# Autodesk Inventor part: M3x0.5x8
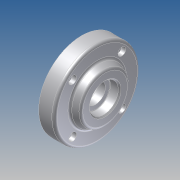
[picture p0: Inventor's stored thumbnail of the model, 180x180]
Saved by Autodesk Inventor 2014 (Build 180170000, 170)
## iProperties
Company: 한국ATC센터
Created: 2009-02
Part Number: M3x0.5x8
Document SubType Name: Modeling
Designer: KYOUNG IL JANG
Density: 2.71 g/cm^3
Mass: 114.339 g
Surface Area: 117.889 cm^2
Volume: 42.1916 cm^3
Material: 알루미늄-6061
Vendor: CBT Solutions
Appearance: 알루미늄 - 평지
Author: KYOUNG IL JANG
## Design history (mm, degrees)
sketch "스케치1"
  geometry: L1 (-11.5, 0)-(11.5, 0); L2 (11.5, 0)-(11.5, 22.5); L3 (11.5, 22.5)-(6.5, 22.5); L4 (6.5, 22.5)-(6.5, 32.5); L5 (6.5, 32.5)-(-5.5, 32.5); L6 (-5.5, 32.5)-(-5.5, 21); L7 (-5.5, 21)-(-11.5, 18.202); L8 (-11.5, 18.202)-(-11.5, 0); 2 further points
  constraints: 16 end point, 3 parallel, 3 perpendicular, 1 coincident, 1 horizontal, 1 midpoint
  dimensions: "d0" = 23 distance of L1.start L1.end; "d1" = 65 diameter of L5 L1; "d2" = 45 diameter of L3 L1; "d3" = 42 diameter of L6.end L1; "d4" = 115 deg angle of L7 L6; "d5" = 12 distance of L4.end L5.end; "d6" = 5 distance of L2.end L3.end
revolve "회전1" sketch "스케치1" stored, may be unused: angle "d7" = 90 deg
sketch "스케치2"
  geometry: L1 (0, 0)-(32.5, 0); L2 (0, 0)-(18.738, 18.738); 1 further point
  constraints: 4 end point, 1 horizontal, 1 horizontal alignment, 1 other
  dimensions: "d8" = 45 deg angle of L1 L2; "d9" = 26.5 distance of L1.start L2.end
hole "구멍1" sketch "스케치2" at (18.738, 18.738) diameter "d10" = 3.4; stored, may be unused: countersink angle "d14" = 90 deg, drill point angle "d16" = 118 deg; dims "d11" = 6, "d12" = 6, "d13" = 3.3, "d15" = 8
fillet "모깎기1" dims "d20" = 2
hole "구멍2" diameter "d23" = 15; stored, may be unused: countersink angle "d27" = 90 deg, drill point angle "d29" = 118 deg; dims "d21" = 10, "d22" = 10, "d24" = 6, "d25" = 32, "d26" = 10, "d28" = 8
hole "구멍3" diameter "d32" = 22; stored, may be unused: countersink angle "d36" = 90 deg, drill point angle "d38" = 0 deg; dims "d30" = 10, "d31" = 10, "d33" = 6, "d34" = 32, "d35" = 10, "d37" = 7.3
chamfer "모따기1" distance "d39" = 1; stored, may be unused: second distance "d40" = 2, angle "d41" = 45 deg
fillet "모깎기2" dims "d42" = 0.3
node "솔리드1"
pattern_circular "원형 패턴1" dims angle "d18" = 360 deg
